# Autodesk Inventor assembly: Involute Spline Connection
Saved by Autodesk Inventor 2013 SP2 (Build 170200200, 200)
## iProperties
Created: 2020-02
Part Number: Involute Spline Connection
Document SubType Name: Assembly
Designer: DELL
ClientObjectVersion: 1
Author: DELL
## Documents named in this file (1)
- C:\Users\DELL\Dropbox\Inventor\Projects\Quadcopter F450\Assemblies\Servo - Design Accelerator Spline Tutorial\Servo - Design Accelerator Spline Tutorial 5.2 Shaft\Design Accelerator\Involute Spline Connection1.iam
